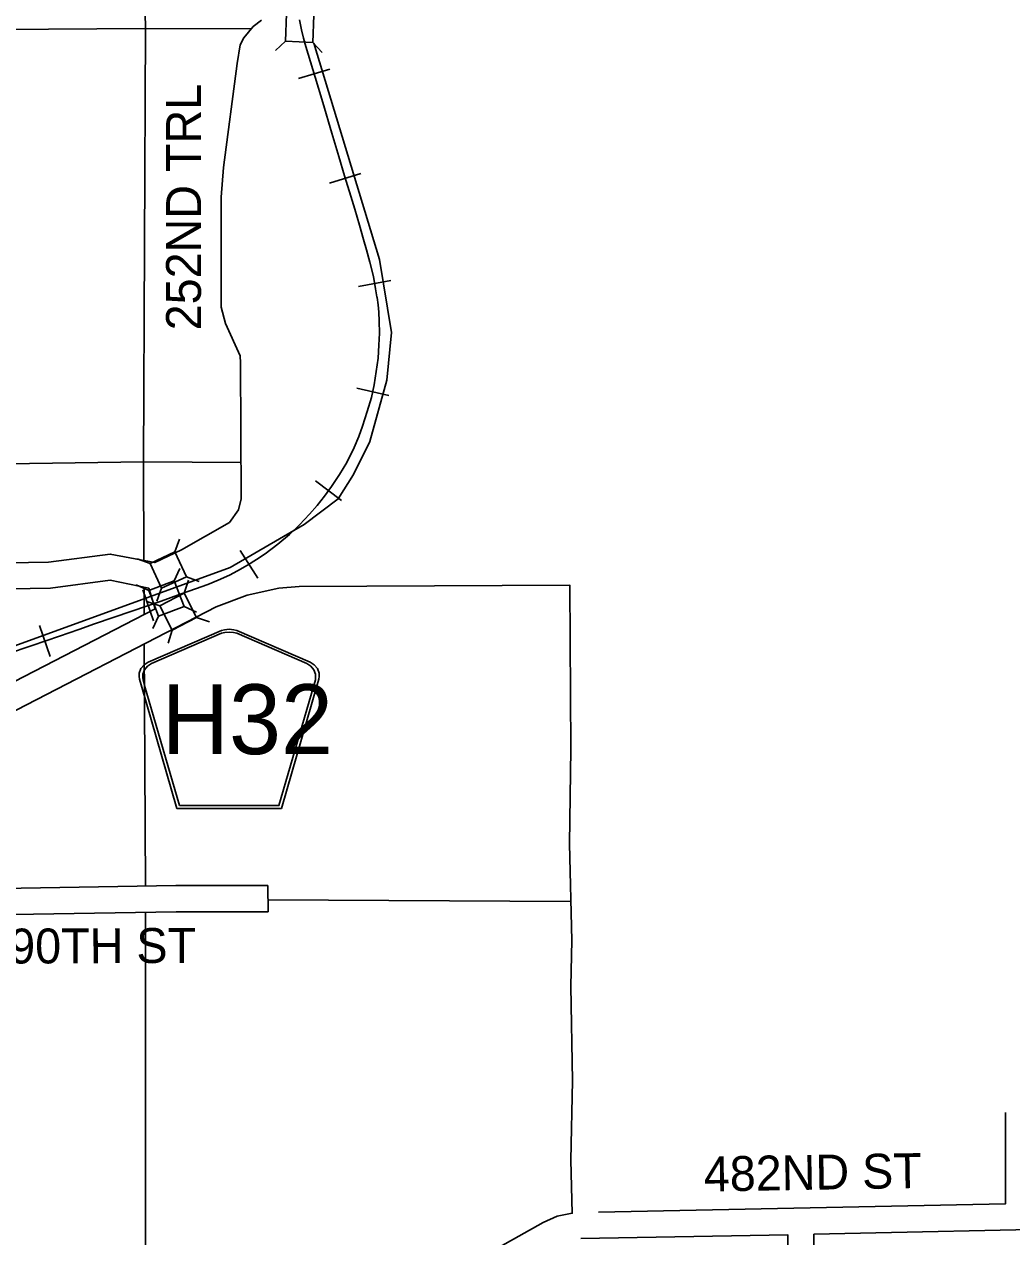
# Model space of a CAD drawing. Extents: x 10133 to 81668, y 5524 to 11018.
# Drawn here: x 18733.6 to 19016.4, y 8478.4 to 8825.6 of the extents above; entities that cross this region are included whole.
import ezdxf

# ---------------------------------------------------------------- set-up
doc = ezdxf.new("R2010")
doc.units = 0
doc.layers.add('Default', color=7, linetype='Continuous')

msp = doc.modelspace()

# ---------------------------------------------------------------- linework, layer by layer
at = {"layer": 'Default'}
for p, q in [((18808.42, 8820.73), (18805.54, 8818.08)), ((18816.24, 8820.4), (18818.89, 8817.52)), ((18821.12, 8812.76), (18812.15, 8810.06)), ((18830.03, 8782.83), (18821.07, 8780.09)), ((18838.55, 8752.23), (18829.34, 8750.51)), ((18837.97, 8719.32), (18828.83, 8721.38)), ((18824.48, 8689.22), (18816.98, 8694.84)), ((18776.77, 8674.48), (18778.12, 8678.15)), ((18769.66, 8671.21), (18765.99, 8672.57)), ((18800.46, 8666.99), (18795.45, 8674.91)), ((18776.59, 8666.21), (18778.19, 8669.78)), ((18769.28, 8663.43), (18765.71, 8665.04)), ((18779.42, 8662.66), (18780.62, 8666.39)), ((18780.04, 8667.38), (18783.71, 8666.02)), ((18770.6, 8654.73), (18767.57, 8663.6)), ((18772.93, 8664.11), (18771.57, 8660.44)), ((18772.45, 8659.1), (18768.73, 8660.31)), ((18779.37, 8658.9), (18782.94, 8657.3)), ((18772.06, 8656.12), (18770.46, 8652.55)), ((18782.98, 8655.7), (18786.7, 8654.49)), ((18741.08, 8644.55), (18738, 8653.4)), ((18776.01, 8652.13), (18774.81, 8648.41))]:
    msp.add_line(p, q, dxfattribs=at)
for points in [[(18767.09, 8883.04), (18768.33, 8824.32)], [(18711.63, 8671.1), (18740.6, 8671.58), (18758.27, 8673.87), (18771, 8671.44), (18778.65, 8675.1), (18792.36, 8682.93), (18794.97, 8686.59), (18795.74, 8689.68), (18795.59, 8728.65), (18795.41, 8730.61), (18791.23, 8739.94), (18789.97, 8744.59), (18789.98, 8776.08), (18790.65, 8784.6), (18794.55, 8814.34), (18795.44, 8819.66), (18796.46, 8821.68), (18799.16, 8824.91), (18801.6, 8826.71)], [(18728.59, 8645.24), (18735.86, 8647.7), (18743.7, 8650.42), (18749.27, 8652.32), (18753.79, 8653.89), (18764.41, 8657.56), (18772.83, 8660.44), (18778.56, 8662.47), (18782.66, 8663.92), (18786.16, 8665.19), (18789.15, 8666.41), (18792.36, 8667.88), (18794.72, 8669.13), (18797.5, 8670.67), (18800.09, 8672.31), (18802.58, 8673.98), (18806.22, 8676.73), (18809.59, 8679.51), (18812.44, 8682.27), (18815.29, 8685.28), (18817.52, 8687.84), (18819.55, 8690.46), (18821.62, 8693.21), (18823.91, 8696.65), (18825.94, 8700.06), (18828.07, 8704.42), (18829.38, 8707.56), (18830.43, 8710.48), (18831.84, 8714.67), (18833.02, 8718.67), (18833.84, 8722.31), (18834.43, 8726.14), (18834.92, 8729.94), (18835.15, 8733.65), (18835.31, 8737.09), (18835.25, 8740.56), (18835.12, 8743.15), (18834.92, 8745.21), (18834.63, 8747.38), (18834.6, 8747.56), (18834.23, 8749.83), (18833.58, 8753.34), (18832.6, 8757.47), (18831.58, 8761.04), (18830.73, 8763.96), (18829.58, 8768.09), (18828.24, 8772.61), (18827.12, 8776.31), (18825.32, 8782.21), (18823.72, 8787.68), (18821.68, 8794.4), (18819.09, 8803.21), (18816.93, 8810.42), (18814.28, 8819.24), (18813.62, 8821.63), (18813.03, 8823.99), (18812.44, 8826.8)], [(18728.59, 8645.24), (18735.86, 8647.7), (18743.7, 8650.42), (18749.27, 8652.32), (18753.79, 8653.89), (18764.41, 8657.56), (18772.83, 8660.44), (18778.56, 8662.47), (18782.66, 8663.92), (18786.16, 8665.19), (18789.15, 8666.41), (18792.36, 8667.88), (18794.72, 8669.13), (18797.5, 8670.67), (18800.09, 8672.31), (18802.58, 8673.98), (18806.22, 8676.73), (18809.59, 8679.51), (18812.44, 8682.27), (18815.29, 8685.28), (18817.52, 8687.84), (18819.55, 8690.46), (18821.62, 8693.21), (18823.91, 8696.65), (18825.94, 8700.06), (18828.07, 8704.42), (18829.38, 8707.56), (18830.43, 8710.48), (18831.84, 8714.67), (18833.02, 8718.67), (18833.84, 8722.31), (18834.43, 8726.14), (18834.92, 8729.94), (18835.15, 8733.65), (18835.31, 8737.09), (18835.25, 8740.56), (18835.12, 8743.15), (18834.92, 8745.21), (18834.63, 8747.38), (18834.6, 8747.56), (18834.23, 8749.83), (18833.58, 8753.34), (18832.6, 8757.47), (18831.58, 8761.04), (18830.73, 8763.96), (18829.58, 8768.09), (18828.24, 8772.61), (18827.12, 8776.31), (18825.32, 8782.21), (18823.72, 8787.68), (18821.68, 8794.4), (18819.09, 8803.21), (18816.93, 8810.42), (18814.28, 8819.24), (18813.62, 8821.63), (18813.03, 8823.99), (18812.44, 8826.8)], [(18728.59, 8645.24), (18735.86, 8647.7), (18743.7, 8650.42), (18749.27, 8652.32), (18753.79, 8653.89), (18764.41, 8657.56), (18772.83, 8660.44), (18778.56, 8662.47), (18782.66, 8663.92), (18786.16, 8665.19), (18789.15, 8666.41), (18792.36, 8667.88), (18794.72, 8669.13), (18797.5, 8670.67), (18800.09, 8672.31), (18802.58, 8673.98), (18806.22, 8676.73), (18809.59, 8679.51), (18812.44, 8682.27), (18815.29, 8685.28), (18817.52, 8687.84), (18819.55, 8690.46), (18821.62, 8693.21), (18823.91, 8696.65), (18825.94, 8700.06), (18828.07, 8704.42), (18829.38, 8707.56), (18830.43, 8710.48), (18831.84, 8714.67), (18833.02, 8718.67), (18833.84, 8722.31), (18834.43, 8726.14), (18834.92, 8729.94), (18835.15, 8733.65), (18835.31, 8737.09), (18835.25, 8740.56), (18835.12, 8743.15), (18834.92, 8745.21), (18834.63, 8747.38), (18834.6, 8747.56), (18834.23, 8749.83), (18833.58, 8753.34), (18832.6, 8757.47), (18831.58, 8761.04), (18830.73, 8763.96), (18829.58, 8768.09), (18828.24, 8772.61), (18827.12, 8776.31), (18825.32, 8782.21), (18823.72, 8787.68), (18821.68, 8794.4), (18819.09, 8803.21), (18816.93, 8810.42), (18814.28, 8819.24), (18813.62, 8821.63), (18813.03, 8823.99), (18812.44, 8826.8)], [(18643.17, 8823.5), (18768.33, 8824.32)], [(18768.33, 8824.32), (18767.78, 8700.3)], [(18768.33, 8824.32), (18798.63, 8824.31)], [(18823.53, 8689.73), (18827.85, 8696.65), (18832.55, 8706.13), (18837.43, 8723.71), (18838.76, 8737.33), (18835.34, 8758.23), (18816.58, 8820.13)], [(18823.53, 8689.73), (18827.85, 8696.65), (18832.55, 8706.13), (18837.43, 8723.71), (18838.76, 8737.33), (18835.34, 8758.23), (18816.58, 8820.13)], [(18643.7, 8698.51), (18767.78, 8700.3)], [(18767.78, 8700.3), (18795.68, 8700.14)], [(18767.78, 8700.3), (18767.91, 8671.99)], [(18792.63, 8670.07), (18813.81, 8682.31), (18823.53, 8689.73)], [(18792.63, 8670.07), (18813.81, 8682.31), (18823.53, 8689.73)], [(18624.27, 8544.87), (18635.01, 8578.45), (18645.39, 8604.53), (18651.48, 8611.45), (18658.37, 8617), (18709.8, 8639.99), (18792.63, 8670.07)], [(18624.27, 8544.87), (18635.01, 8578.45), (18645.39, 8604.53), (18651.48, 8611.45), (18658.37, 8617), (18709.8, 8639.99), (18792.63, 8670.07)], [(18719.1, 8631.37), (18771.11, 8658.24), (18769.28, 8664.09), (18758.22, 8666.37), (18741.14, 8664.1), (18711.72, 8663.6)], [(18837.18, 8457.2), (18882.24, 8482.55), (18886.25, 8484.3), (18890.53, 8485.18), (18890.09, 8500.38), (18890.55, 8523.04), (18890.09, 8550.19), (18890.37, 8563.24), (18889.69, 8590.91), (18890.15, 8618), (18889.81, 8665), (18812.3, 8664.64), (18806.56, 8664.1), (18797.48, 8662.08), (18788.62, 8658.74), (18722.71, 8624.8)], [(18767.94, 8664.27), (18767.98, 8656.61)], [(18768.01, 8648.18), (18768.32, 8578.82)], [(18704.99, 8577.72), (18776.99, 8578.97), (18803.36, 8578.98), (18803.44, 8571.48), (18777.1, 8571.47), (18701.19, 8570.18)], [(18803.41, 8574.88), (18890.02, 8574.46)], [(18768.34, 8571.32), (18768.32, 8453.2)], [(18898.03, 8485.5), (19014.59, 8487.9), (19014.59, 8509.93), (19014.58, 8514.04)], [(18952.07, 8399.04), (18952.23, 8478.98), (18893.02, 8477.95)], [(19039.8, 8480.87), (18959.72, 8479.16), (18959.57, 8399.1)]]:
    msp.add_lwpolyline(points, dxfattribs=at)
for points in [[(18808.75, 8828.55), (18816.57, 8828.22), (18816.24, 8820.4), (18808.42, 8820.73)], [(18769.66, 8671.21), (18776.77, 8674.48), (18780.04, 8667.38), (18772.93, 8664.11)], [(18769.28, 8663.43), (18776.59, 8666.21), (18779.37, 8658.9), (18772.06, 8656.12)], [(18772.45, 8659.1), (18779.42, 8662.66), (18782.98, 8655.7), (18776.01, 8652.13)], [(18777.33, 8601.07), (18767.09, 8636.43), (18766.6, 8638.08), (18766.51, 8638.81), (18766.51, 8639.79), (18767.04, 8641.08), (18767.95, 8642.14), (18769.15, 8642.97), (18790.06, 8652.02), (18791, 8652.22), (18792.3, 8652.34), (18793.6, 8652.22), (18794.54, 8652.02), (18815.45, 8642.97), (18816.65, 8642.14), (18817.56, 8641.08), (18818.09, 8639.79), (18818.09, 8638.81), (18818, 8638.08), (18817.51, 8636.43), (18807.27, 8601.07)], [(18778.06, 8601.86), (18768.1, 8636.27), (18767.63, 8637.85), (18767.54, 8638.55), (18767.54, 8639.49), (18768.05, 8640.73), (18768.92, 8641.75), (18770.07, 8642.55), (18790.15, 8651.23), (18791.05, 8651.43), (18792.3, 8651.54), (18793.55, 8651.43), (18794.45, 8651.23), (18814.53, 8642.55), (18815.67, 8641.75), (18816.55, 8640.73), (18817.06, 8639.49), (18817.06, 8638.55), (18816.97, 8637.85), (18816.5, 8636.27), (18806.54, 8601.86)]]:
    msp.add_lwpolyline(points, close=True, dxfattribs=at)

# ---------------------------------------------------------------- texts
for s, rotation, p in [('252ND TRL', 90, (18784.23, 8737.94)), ('490TH ST', 0.2303, (18721.9, 8556.61)), ('482ND ST', 0.9556, (18928.26, 8491.36))]:
    msp.add_text(s, height=10, rotation=rotation, dxfattribs=at).set_placement(p)
msp.add_text('H32', height=20, dxfattribs=at).set_placement((18772.95, 8616.6))

doc.saveas('drawing.dxf')
